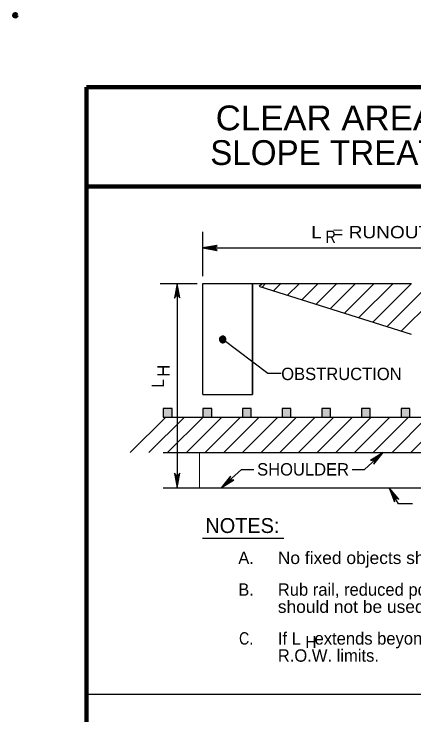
# Model space of a CAD drawing. Extents: x 11.149 to 11.823, y 1.038 to 1.922.
# Drawn here: x 11.1485 to 11.4007, y 1.4804 to 1.9224 of the extents above; entities that cross this region are included whole.
import ezdxf
from ezdxf.enums import TextEntityAlignment as Align

# ---------------------------------------------------------------- set-up
doc = ezdxf.new("R2010")
doc.units = 0
doc.header["$LTSCALE"] = 0.0031
doc.header["$PDMODE"] = 32
doc.header["$PDSIZE"] = 0.00155
doc.linetypes.add('LONG_DASHED', pattern=[7.5, 6, -1.5])
for name, color, linetype, lineweight in [('1', 7, 'Continuous', 90), ('24', 7, 'Continuous', 25), ('40', 7, 'Continuous', 25), ('5', 7, 'LONG_DASHED', 25), ('60', 7, 'Continuous', 25)]:
    doc.layers.add(name, color=color, linetype=linetype, lineweight=lineweight)

msp = doc.modelspace()

# ---------------------------------------------------------------- hatches: boundary and pattern name
at = {"layer": '60'}
for points in [[(11.242575, 1.673642), (11.242575, 1.668092), (11.248133, 1.668092), (11.248133, 1.673642)], [(11.267575, 1.673642), (11.267575, 1.668092), (11.273133, 1.668092), (11.273133, 1.673642)], [(11.292575, 1.673642), (11.292575, 1.668092), (11.298133, 1.668092), (11.298133, 1.673642)], [(11.317575, 1.673642), (11.317575, 1.668092), (11.323133, 1.668092), (11.323133, 1.673642)], [(11.342575, 1.673642), (11.342575, 1.668092), (11.348133, 1.668092), (11.348133, 1.673642)], [(11.367575, 1.673642), (11.367575, 1.668092), (11.373125, 1.668092), (11.373125, 1.673642)], [(11.392575, 1.673642), (11.392575, 1.668092), (11.398125, 1.668092), (11.398125, 1.673642)]]:
    msp.add_hatch(color=256, dxfattribs=at).paths.add_polyline_path(points)

# ---------------------------------------------------------------- linework, layer by layer
at = {"layer": '1'}
for p, q in [((11.194317, 1.876217), (11.77765, 1.876217)), ((11.194317, 1.08455), (11.194317, 1.876217)), ((11.194317, 1.813717), (11.77765, 1.813717))]:
    msp.add_line(p, q, dxfattribs=at)
at = {"layer": '1', "lineweight": 13}
msp.add_line((11.2654, 1.645867), (11.2654, 1.623642), dxfattribs=at)
at = {"layer": '1', "lineweight": 25}
for p, q in [((11.292042, 1.635283), (11.299633, 1.635283)), ((11.361775, 1.635283), (11.369475, 1.635283)), ((11.194317, 1.493575), (11.77765, 1.493575))]:
    msp.add_line(p, q, dxfattribs=at)
at = {"layer": '1'}
msp.add_point((11.149317, 1.921633), dxfattribs=at)
at = {"layer": '24'}
for p, q in [((11.267575, 1.757183), (11.267575, 1.785133)), ((11.267383, 1.774867), (11.704592, 1.774867)), ((11.240575, 1.752542), (11.263958, 1.752542)), ((11.251408, 1.752542), (11.251408, 1.623642)), ((11.307092, 1.752542), (11.304933, 1.750158)), ((11.242575, 1.668092), (11.462017, 1.668092)), ((11.242575, 1.645867), (11.650125, 1.645867)), ((11.381158, 1.645867), (11.369475, 1.635283)), ((11.292042, 1.635283), (11.279192, 1.623642)), ((11.242642, 1.623642), (11.742692, 1.623642)), ((11.267367, 1.591825), (11.318642, 1.591825))]:
    msp.add_line(p, q, dxfattribs=at)
for points in [[(11.267383, 1.774867), (11.276617, 1.773233), (11.274408, 1.774867), (11.276575, 1.776467), (11.267383, 1.774867), (11.267992, 1.774883), (11.276358, 1.77335), (11.274242, 1.774883), (11.2762, 1.776342), (11.268325, 1.774908), (11.268633, 1.774867), (11.2758, 1.773592), (11.274192, 1.774883), (11.275842, 1.776133), (11.268775, 1.774858), (11.269083, 1.774908), (11.275342, 1.773775), (11.274125, 1.774858), (11.275367, 1.775992), (11.269975, 1.774908), (11.270492, 1.774908), (11.274883, 1.774008), (11.274025, 1.774833), (11.27495, 1.775758), (11.270583, 1.774867), (11.271083, 1.774833), (11.274375, 1.774267), (11.273742, 1.774908), (11.274433, 1.775542), (11.271533, 1.774867), (11.272, 1.774817), (11.273983, 1.774433), (11.27365, 1.774883), (11.274192, 1.775375), (11.272242, 1.774858), (11.273533, 1.774558), (11.273342, 1.774908), (11.273908, 1.775267), (11.272567, 1.774908), (11.273417, 1.7747), (11.273058, 1.774975), (11.273467, 1.775142), (11.273058, 1.774883), (11.273275, 1.774833)], [(11.251408, 1.752542), (11.249775, 1.7433), (11.251408, 1.745508), (11.253017, 1.74335), (11.251408, 1.752542), (11.251425, 1.751933), (11.2499, 1.743567), (11.251425, 1.745683), (11.252892, 1.743725), (11.251458, 1.7516), (11.251408, 1.751292), (11.250133, 1.744125), (11.251425, 1.745733), (11.252683, 1.744075), (11.251408, 1.75115), (11.251458, 1.750842), (11.250325, 1.744575), (11.251408, 1.7458), (11.252533, 1.74455), (11.251458, 1.74995), (11.251458, 1.749433), (11.250558, 1.745042), (11.251383, 1.7459), (11.2523, 1.744975), (11.251408, 1.749333), (11.251383, 1.748842), (11.250817, 1.745542), (11.251458, 1.746175), (11.252092, 1.745492), (11.251408, 1.748392), (11.251358, 1.747925), (11.250983, 1.745942), (11.251425, 1.746267), (11.251925, 1.745733), (11.251408, 1.747683), (11.2511, 1.746392), (11.251458, 1.746575), (11.251808, 1.746008), (11.251458, 1.747358), (11.251242, 1.746508), (11.251525, 1.746867), (11.251692, 1.746458), (11.251425, 1.746867), (11.251383, 1.74665)], [(11.316883, 1.695692), (11.308483, 1.695692), (11.280092, 1.717217)], [(11.381158, 1.645867), (11.373183, 1.640925), (11.375925, 1.641175), (11.375383, 1.638542), (11.381158, 1.645867), (11.380717, 1.645442), (11.373458, 1.641008), (11.376058, 1.641275), (11.375575, 1.638883), (11.380483, 1.6452), (11.380217, 1.645033), (11.374033, 1.6412), (11.376092, 1.641308), (11.3757, 1.639267), (11.380117, 1.644933), (11.379925, 1.6447), (11.3745, 1.641358), (11.376133, 1.641367), (11.375958, 1.639692), (11.37925, 1.644108), (11.378867, 1.643758), (11.375, 1.641492), (11.376183, 1.64145), (11.376117, 1.640158), (11.378767, 1.643733), (11.378383, 1.643417), (11.37555, 1.641642), (11.37645, 1.641592), (11.376358, 1.640658), (11.378067, 1.6431), (11.377683, 1.642825), (11.375958, 1.641783), (11.3765, 1.641667), (11.376425, 1.640933), (11.377542, 1.642625), (11.376367, 1.641992), (11.376742, 1.641858), (11.37655, 1.641208), (11.377325, 1.642367), (11.37655, 1.641967), (11.377, 1.641992), (11.376808, 1.6416), (11.376942, 1.642067), (11.37675, 1.641958)], [(11.251408, 1.623642), (11.253042, 1.632883), (11.251408, 1.630675), (11.2498, 1.632833), (11.251408, 1.623642), (11.251392, 1.624258), (11.252925, 1.632625), (11.251392, 1.630508), (11.249925, 1.632467), (11.251367, 1.624592), (11.251408, 1.6249), (11.252683, 1.632067), (11.251392, 1.630458), (11.250133, 1.632108), (11.251408, 1.625042), (11.251367, 1.625342), (11.252492, 1.631608), (11.251408, 1.630392), (11.250283, 1.631633), (11.251358, 1.626242), (11.251367, 1.626758), (11.252258, 1.63115), (11.251433, 1.630292), (11.250517, 1.631208), (11.251408, 1.62685), (11.251433, 1.627342), (11.252, 1.630642), (11.251358, 1.630008), (11.250733, 1.6307), (11.251408, 1.6278), (11.251458, 1.628267), (11.251833, 1.630242), (11.251392, 1.629917), (11.250892, 1.630458), (11.251408, 1.628508), (11.251717, 1.6298), (11.251367, 1.629608), (11.251008, 1.630175), (11.251358, 1.628833), (11.251575, 1.629675), (11.251292, 1.629325), (11.251125, 1.629733), (11.251392, 1.629325), (11.251433, 1.629542)], [(11.279192, 1.623642), (11.287142, 1.628633), (11.284408, 1.628367), (11.284925, 1.631008), (11.279192, 1.623642), (11.279642, 1.624067), (11.286867, 1.62855), (11.284267, 1.628267), (11.284733, 1.630658), (11.279867, 1.624308), (11.280125, 1.624483), (11.286292, 1.62835), (11.284233, 1.628233), (11.284608, 1.630275), (11.280225, 1.624575), (11.280425, 1.624817), (11.285825, 1.628192), (11.284192, 1.628175), (11.284358, 1.629842), (11.281083, 1.625417), (11.281475, 1.625767), (11.285325, 1.62805), (11.284142, 1.628083), (11.2842, 1.629383), (11.281575, 1.625792), (11.281958, 1.626108), (11.284783, 1.6279), (11.283875, 1.62795), (11.283967, 1.628883), (11.282275, 1.626433), (11.28265, 1.626708), (11.284367, 1.627758), (11.283833, 1.627867), (11.2839, 1.6286), (11.2828, 1.626908), (11.283958, 1.62755), (11.283583, 1.627683), (11.283767, 1.628325), (11.283008, 1.627158), (11.283775, 1.627575), (11.283325, 1.627542), (11.283517, 1.627933), (11.283392, 1.627475), (11.283575, 1.627583)], [(11.399675, 1.613558), (11.390975, 1.613558), (11.385042, 1.623642)], [(11.385042, 1.623642), (11.388317, 1.61485), (11.3886, 1.617583), (11.391083, 1.616542), (11.385042, 1.623642), (11.385367, 1.623125), (11.388292, 1.615133), (11.388533, 1.617742), (11.390783, 1.616792), (11.385558, 1.62285), (11.385675, 1.622567), (11.388208, 1.615742), (11.388508, 1.617783), (11.390425, 1.616992), (11.385742, 1.622442), (11.385942, 1.6222), (11.388142, 1.616225), (11.388458, 1.617833), (11.390058, 1.617325), (11.386392, 1.621433), (11.386658, 1.620983), (11.388108, 1.61675), (11.388383, 1.6179), (11.389642, 1.617575), (11.386667, 1.620883), (11.386892, 1.620442), (11.388075, 1.617308), (11.388308, 1.618183), (11.3892, 1.617908), (11.387142, 1.620067), (11.387342, 1.619642), (11.388017, 1.617742), (11.388233, 1.61825), (11.388933, 1.618033), (11.3875, 1.619458), (11.387892, 1.618183), (11.3881, 1.618525), (11.388692, 1.618217), (11.387708, 1.6192), (11.387958, 1.618358), (11.388017, 1.618808), (11.388367, 1.618542), (11.387933, 1.618758), (11.388, 1.61855)]]:
    msp.add_lwpolyline(points, dxfattribs=at)
for radius, start, end in [(0.002083, 142.82501, 322.82501), (0.002014, 142.82501, 322.82501), (0.001944, 142.82501, 322.82501), (0.001875, 142.82501, 322.82501), (0.001806, 142.82501, 322.82501), (0.001736, 142.82501, 322.82501), (0.001667, 142.82501, 322.82501), (0.002083, 322.82501, 142.82501), (0.002014, 322.82501, 142.82501), (0.001597, 142.82501, 322.82501), (0.001944, 322.82501, 142.82501), (0.001528, 142.82501, 322.82501), (0.001875, 322.82501, 142.82501), (0.001458, 142.82501, 322.82501), (0.001806, 322.82501, 142.82501), (0.001389, 142.82501, 322.82501), (0.001736, 322.82501, 142.82501), (0.001667, 322.82501, 142.82501), (0.001319, 142.82501, 322.82501), (0.001597, 322.82501, 142.82501), (0.00125, 142.82501, 322.82501), (0.001528, 322.82501, 142.82501), (0.001181, 142.82501, 322.82501), (0.001458, 322.82501, 142.82501), (0.001111, 142.82501, 322.82501), (0.001389, 322.82501, 142.82501), (0.001319, 322.82501, 142.82501), (0.001042, 142.82501, 322.82501), (0.00125, 322.82501, 142.82501), (0.000972, 142.82501, 322.82501), (0.001181, 322.82501, 142.82501), (0.000903, 142.82501, 322.82501), (0.001111, 322.82501, 142.82501), (0.000833, 142.82501, 322.82501), (0.001042, 322.82501, 142.82501), (0.000972, 322.82501, 142.82501), (0.000764, 142.82501, 322.82501), (0.000903, 322.82501, 142.82501), (0.000694, 142.82501, 322.82501), (0.000833, 322.82501, 142.82501), (0.000625, 142.82501, 322.82501), (0.000764, 322.82501, 142.82501), (0.000556, 142.82501, 322.82501), (0.000694, 322.82501, 142.82501), (0.000625, 322.82501, 142.82501), (0.000486, 142.82501, 322.82501), (0.000556, 322.82501, 142.82501), (0.000417, 142.82501, 322.82501), (0.000486, 322.82501, 142.82501), (0.000347, 142.82501, 322.82501), (0.000417, 322.82501, 142.82501), (0.000278, 142.82501, 322.82501), (0.000347, 322.82501, 142.82501), (0.000278, 322.82501, 142.82501), (0.000208, 142.82501, 322.82501), (0.000208, 322.82501, 142.82501), (0.000139, 142.82501, 322.82501), (0.000139, 322.82501, 142.82501), (0.0000694, 142.82501, 322.82501), (0.0000694, 322.82501, 142.82501)]:
    msp.add_arc((11.280095, 1.71722), radius, start, end, dxfattribs=at)
at = {"layer": '40'}
for p, q in [((11.303117, 1.750733), (11.304683, 1.7523)), ((11.312075, 1.747908), (11.316475, 1.752308)), ((11.321033, 1.745083), (11.328275, 1.752317)), ((11.329992, 1.74225), (11.340067, 1.752325)), ((11.33895, 1.739425), (11.351867, 1.752342)), ((11.347908, 1.736592), (11.363658, 1.75235)), ((11.356858, 1.733767), (11.37545, 1.752358)), ((11.365817, 1.730942), (11.38725, 1.752367)), ((11.374775, 1.728108), (11.399042, 1.752383)), ((11.383733, 1.725283), (11.410842, 1.752392)), ((11.392692, 1.722458), (11.422633, 1.7524)), ((11.221825, 1.645867), (11.244017, 1.668058)), ((11.233608, 1.645867), (11.255775, 1.668033)), ((11.245392, 1.645867), (11.267533, 1.668008)), ((11.257175, 1.645867), (11.2793, 1.667992)), ((11.268958, 1.645867), (11.291058, 1.667967)), ((11.28075, 1.645867), (11.302825, 1.667942)), ((11.292533, 1.645867), (11.314583, 1.667917)), ((11.304317, 1.645867), (11.326342, 1.667892)), ((11.3161, 1.645867), (11.338108, 1.667875)), ((11.327892, 1.645867), (11.350108, 1.668092)), ((11.339675, 1.645867), (11.3619, 1.668092)), ((11.351458, 1.645867), (11.373683, 1.668092)), ((11.363242, 1.645867), (11.385467, 1.668092)), ((11.375025, 1.645867), (11.39725, 1.668092)), ((11.386817, 1.645867), (11.409033, 1.668092)), ((11.3986, 1.645867), (11.420825, 1.668092))]:
    msp.add_line(p, q, dxfattribs=at)
at = {"layer": '5', "linetype": 'Continuous'}
for p, q in [((11.267575, 1.682567), (11.267575, 1.752542)), ((11.298883, 1.682567), (11.298883, 1.752542)), ((11.267575, 1.682567), (11.298883, 1.682567))]:
    msp.add_line(p, q, dxfattribs=at)
at = {"layer": '5'}
for p, q in [((11.298883, 1.752542), (11.587775, 1.752542)), ((11.30345, 1.750633), (11.581983, 1.662692))]:
    msp.add_line(p, q, dxfattribs=at)
at = {"layer": '5', "linetype": 'Continuous'}
msp.add_lwpolyline([(11.267575, 1.752542), (11.298883, 1.752542), (11.298883, 1.682567)], dxfattribs=at)
at = {"layer": '60'}
for points in [[(11.242575, 1.673642), (11.242575, 1.668092), (11.248133, 1.668092), (11.248133, 1.673642)], [(11.267575, 1.673642), (11.267575, 1.668092), (11.273133, 1.668092), (11.273133, 1.673642)], [(11.292575, 1.673642), (11.292575, 1.668092), (11.298133, 1.668092), (11.298133, 1.673642)], [(11.317575, 1.673642), (11.317575, 1.668092), (11.323133, 1.668092), (11.323133, 1.673642)], [(11.342575, 1.673642), (11.342575, 1.668092), (11.348133, 1.668092), (11.348133, 1.673642)], [(11.367575, 1.673642), (11.367575, 1.668092), (11.373125, 1.668092), (11.373125, 1.673642)], [(11.392575, 1.673642), (11.392575, 1.668092), (11.398125, 1.668092), (11.398125, 1.673642)]]:
    msp.add_lwpolyline(points, close=True, dxfattribs=at)

# ---------------------------------------------------------------- texts
at = {"layer": '1'}
for s, height, width, p in [('CLEAR AREA AT S.R.T. AND', 0.01562, 1.05, (11.422521, 1.8491)), ('L  = RUNOUT LENGTH (SEE TABLE-1 IN FIGURE 8-E)', 0.0078, 1.15, (11.485983, 1.780967)), ('R', 0.0078, 0.85, (11.348171, 1.778067)), ('C.', 0.0078, 0.85, (11.294833, 1.524775))]:
    msp.add_text(s, height=height, dxfattribs=dict(at, width=width)).set_placement(p, align=Align.CENTER)
for s, height, p in [('SLOPE TREATMENT AT S.R.T.', 0.01562, (11.422529, 1.827225)), ('OBSTRUCTION', 0.0078, (11.354938, 1.691575)), ('SHOULDER', 0.0078, (11.330763, 1.631383)), ('NOTES:', 0.009375, (11.2925, 1.595142)), ('A.', 0.0078, (11.294837, 1.575575)), ('B.', 0.0078, (11.294829, 1.555575))]:
    msp.add_text(s, height=height, dxfattribs=at).set_placement(p, align=Align.CENTER)
msp.add_text('H', height=0.0078, rotation=90, dxfattribs=at).set_placement((11.2466, 1.697438), align=Align.CENTER)
at = {"layer": '1', "width": 0.9}
msp.add_text('L', height=0.0078, rotation=90, dxfattribs=at).set_placement((11.243175, 1.689525), align=Align.CENTER)
at = {"layer": '1', "width": 1.05}
for s, p in [('No fixed objects should be within the Cross-Hatched area.', (11.314833, 1.575575)), ('should not be used within the 37\'-6" Parabolic Flare.', (11.314833, 1.544775))]:
    msp.add_text(s, height=0.0078, dxfattribs=at).set_placement(p)
at = {"layer": '1'}
for s, height, p in [('Rub rail, reduced post spacing, and double rail elements', 0.0078, (11.314833, 1.555575)), ('If L   extends beyond R.O.W. Line, then clear area only within', 0.0078, (11.314833, 1.524775)), ('H', 0.00741, (11.3321, 1.522708)), ('R.O.W. limits.', 0.0078, (11.314833, 1.513975))]:
    msp.add_text(s, height=height, dxfattribs=at).set_placement(p)

doc.saveas('drawing.dxf')
